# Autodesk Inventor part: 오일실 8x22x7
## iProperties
IsCustomPart: 1
Company: 한국ATC센터
Created: 2014-07
Part Number: 오일실 8x22x7
Material: 고무
Description: 오일-실
Document SubType Name: Modeling
Standard: KS B 2804
Designer: KYOUNG IL JANG
Standards Organization: KS
Language: ko-KR
Size Designation: D - 8 22 7
Categories: <MemberInstance><Categories><Category DisplayName="샤프트 부품" InternalName="7f7aeb1f-a693-4053-b835-cee3144e0d98" Mnemonic="SHFT"><Category DisplayName="실링" Intern
Density: 0.93 g/cm^3
Author: KYOUNG IL JANG
